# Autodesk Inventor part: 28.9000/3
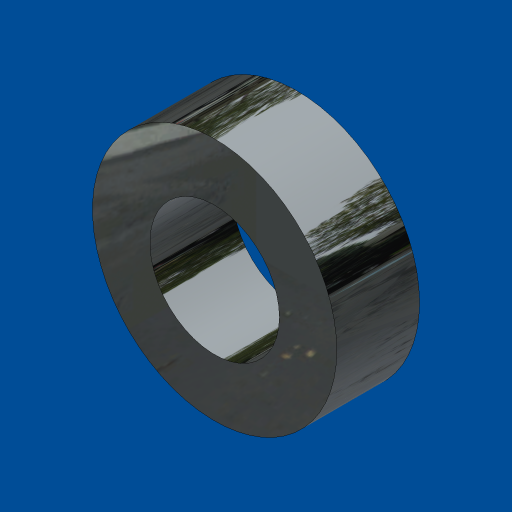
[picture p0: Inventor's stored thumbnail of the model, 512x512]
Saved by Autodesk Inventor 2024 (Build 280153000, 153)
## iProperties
Created: 2022-07
Part Number: 28.9000/3
Material: Aluminum 6061
Document SubType Name: Modeling
Designer: amoles
Density: 2.7 g/cm^3
Appearance: Zinc
Stock Number: 3/4" 6061 AL ROD
Description: ROTATIONAL ELEMENT WASHER
Vendor: F
Mass: 3.5693 g
Surface Area: 10.0063 cm^2
Volume: 1.32196 cm^3
Author: amoles
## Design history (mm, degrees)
sketch "Sketch1"
  geometry: C1 r 5.05 at (0, 0); C2 r 9.525 at (0, 0); 1 further point
  constraints: 2 centre point, 2 coincident
  dimensions: "d0" = 10.1 diameter of C1; "d1" = 19.05 diameter of C2
extrude "Extrusion1" new body sketch "Sketch1" distance "d2" = 6.4516; taper "d3" = 0 deg
body "Solid1"
